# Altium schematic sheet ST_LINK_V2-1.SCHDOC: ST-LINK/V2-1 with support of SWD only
size A4; Date: 29-OCT-2015; Author: A.B; CompanyName: STMicroelectronics; Organization: MCD/TOOLS/GNB; Address1: 12, Rue Jules HOROWITZ; Address2: 38019 Grenoble; Address3: FRANCE; DocumentNumber: MB1225; Revision: B-01; SheetNumber: 2; SheetTotal: 12; Project: STM32F769I-DISCO
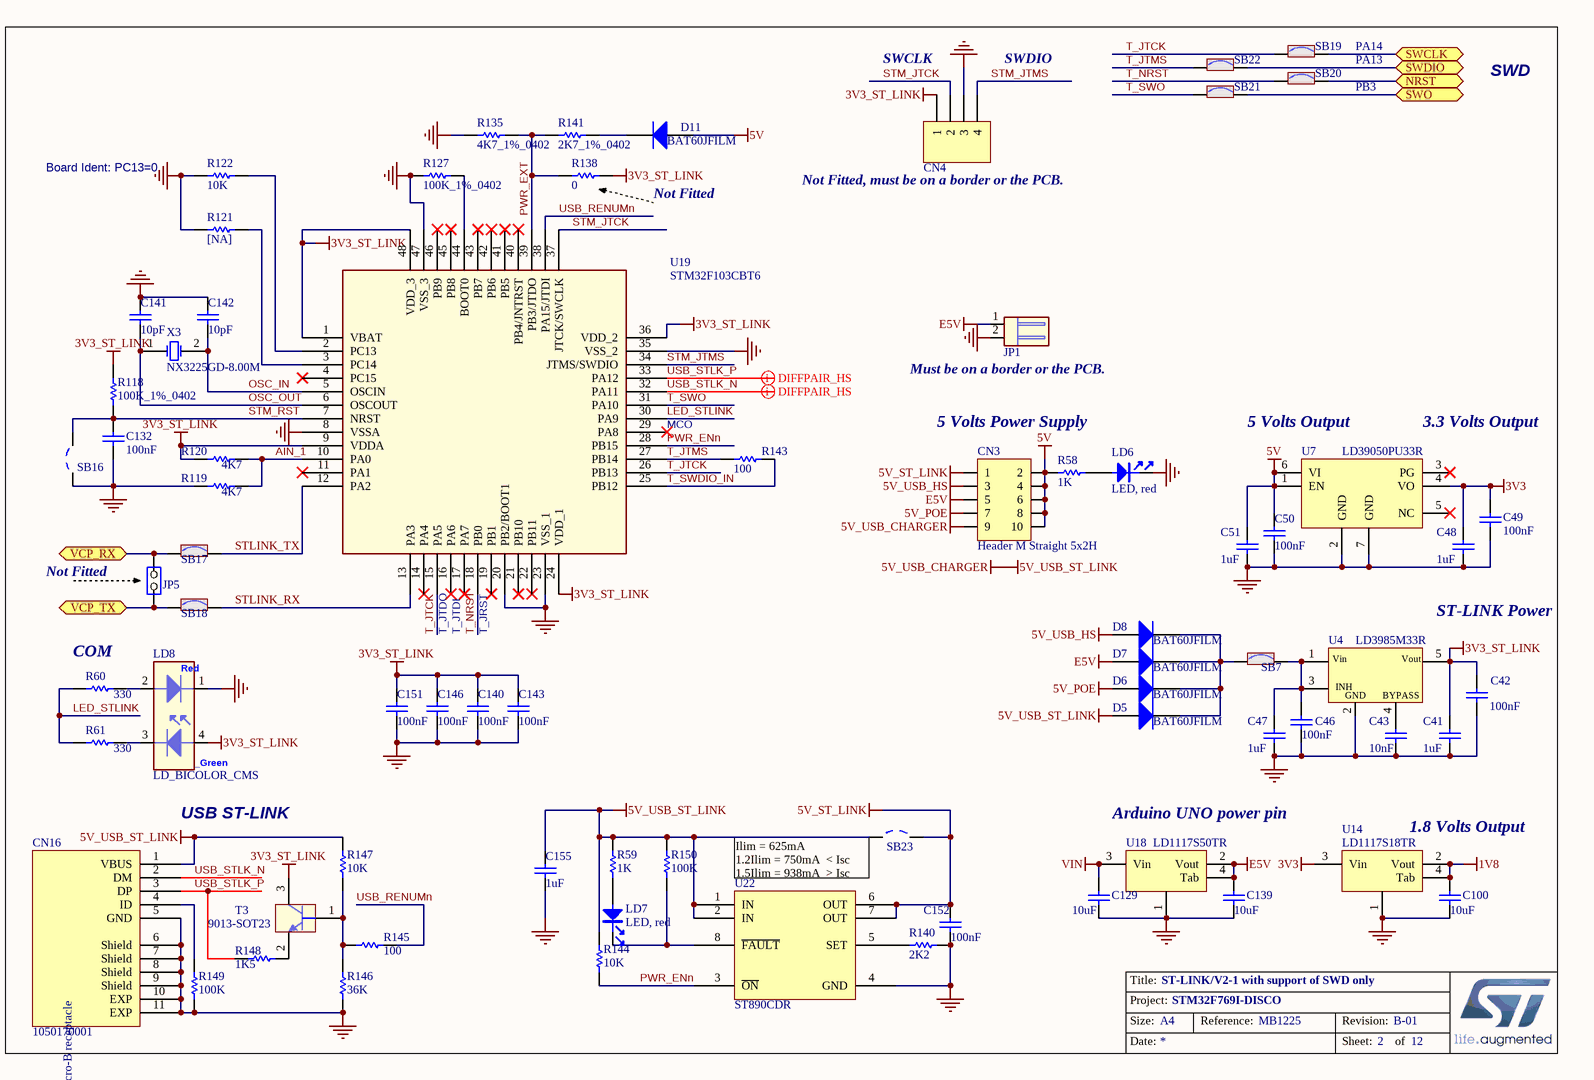
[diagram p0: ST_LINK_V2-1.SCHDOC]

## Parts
C41  1uF  [0603C]
C42  100nF  [0402C]
C43  10nF  [0603C]
C46  100nF  [0402C]
C47  1uF  [0603C]
C48  1uF  [0603C]
C49  100nF  [0402C]
C50  100nF  [0402C]
C51  1uF  [0603C]
C100  10uF  [0603C]
C129  10uF  [0805C]
C132  100nF  [0402C]
C139  10uF  [0805C]
C140  100nF  [0402C]
C141  10pF  [0402C]
C142  10pF  [0402C]
C143  100nF  [0402C]
C146  100nF  [0402C]
C151  100nF  [0402C]
C152  100nF  [0402C]
C155  1uF  [0603C]
CN3  Header M Straight 5x2H  [HDR_2X5_2R54]
CN4  Header 4  [HDR_1X4_2R54]  (value not drawn)
CN16  1050170001  [MICRO_USB_B_105017]
D5  BAT60JFILM  [SOD-323]
D6  BAT60JFILM  [SOD-323]
D7  BAT60JFILM  [SOD-323]
D8  BAT60JFILM  [SOD-323]
D11  BAT60JFILM  [SOD-323]
JP1  WF25402-06421  [HDR_1X2_2R54_RA_11R35]  (value not drawn)
JP5  JP2  [SIP2]  (value not drawn)
LD6  LED, red  [0603D]
LD7  LED, red  [0603D]
LD8  LD_BICOLOR_CMS  [LED2_3528]
R58  1K  [0402R]
R59  1K  [0402R]
R60  330  [0402R]
R61  330  [0402R]
R118  100K_1%_0402  [0402R]
R119  4K7  [0402R]
R120  4K7  [0402R]
R121  [NA]  [0402R]
R122  10K  [0402R]
R127  100K_1%_0402  [0402R]
R135  4K7_1%_0402  [0402R]
R138  0  [0402R]
R140  2K2  [0402R]
R141  2K7_1%_0402  [0402R]
R143  100  [0402R]
R144  10K  [0402R]
R145  100  [0402R]
R146  36K  [0402R]
R147  10K  [0402R]
R148  1K5  [0402R]
R149  100K  [0402R]
R150  100K  [0402R]
SB7  Solder Bridge ON  [JP2_SMD]  (value not drawn)
SB16  Solder Bridge OFF  [JP2_SMD]  (value not drawn)
SB17  Solder Bridge ON  [JP2_SMD]  (value not drawn)
SB18  Solder Bridge ON  [JP2_SMD]  (value not drawn)
SB19  Solder Bridge ON  [JP2_SMD]  (value not drawn)
SB20  Solder Bridge ON  [JP2_SMD]  (value not drawn)
SB21  Solder Bridge ON  [JP2_SMD]  (value not drawn)
SB22  Solder Bridge ON  [JP2_SMD]  (value not drawn)
SB23  Solder Bridge OFF  [JP2_SMD]  (value not drawn)
T3  9013-SOT23  [SOT-23]
U4  LD3985M33R  [SOT-23-5L]
U7  LD39050PU33R  [DFN6_0R95_3X3]
U14  LD1117S18TR  [SOT-223]
U18  LD1117S50TR  [SOT-223]
U19  STM32F103CBT6  [LQFP48_0R5_9X9]
U22  ST890CDR  [SOIC8_1R27_4R9X6]
X3  NX3225GD-8.00M  [XTAL_2SM_3R2X2R5_H1]

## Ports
NRST, SWCLK, SWDIO, SWO, VCP_RX, VCP_TX

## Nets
1V8: C100.2 U14.2(Vout) U14.4(Tab)
3V3: C48.2 C49.2 U7.4(VO) U14.3(Vin)
3V3_ST_LINK: C41.1 C42.2 C140.1 C143.2 C146.2 C151.2 CN4.1 LD8.4 R118.2 R120.1 R138.2 T3.3(C) U4.5(Vout) U19.1(VBAT) U19.9(VDDA) U19.24(VDD_1) U19.36(VDD_2) U19.48(VDD_3)
5V: C50.2 C51.2 CN3.2 CN3.4 CN3.6 CN3.8 CN3.10 D11.1(A) R58.1 U7.1(EN) U7.6(VI)
5V_POE: CN3.7 D6.1(A)
5V_ST_LINK: C152.2 CN3.1 SB23.2 U22.6(OUT) U22.7(OUT)
5V_USB_CHARGER: C155.2 CN3.9 CN16.1(VBUS) D5.1(A) R59.2 R144.2 R147.2 R150.2 SB23.1 U22.1(IN) U22.2(IN)  [also labelled 5V_USB_ST_LINK]
5V_USB_HS: CN3.3 D8.1(A)
E5V: C139.2 CN3.5 D7.1(A) JP1.1 U18.2(Vout) U18.4(Tab)
GND: C41.2 C42.1 C43.1 C46.1 C47.1 C48.1 C49.1 C50.1 C51.1 C100.1 C129.1 C132.1 C139.1 C140.2 C141.1 C142.1 C143.1 C146.1 C151.1 C152.1 C155.1 CN4.3 CN16.5(GND) CN16.6(Shield) CN16.7(Shield) CN16.8(Shield) CN16.9(Shield) CN16.10(EXP) CN16.11(EXP) JP1.2 LD6.2 LD8.1 R119.1 R121.1 R122.1 R127.1 R135.1 R140.2 R146.1 R149.1 SB16.1 U4.2(GND) U7.2(GND) U7.7(GND) U14.1 U18.1 U19.8(VSSA) U19.20(PB2/BOOT1) U19.23(VSS_1) U19.35(VSS_2) U19.47(VSS_3) U22.4(GND)
VIN: C129.2 U18.3(Vin)
AIN_1: R119.2 R120.2 U19.10(PA0)
LED_STLINK: R60.1 R61.1 U19.30(PA9)
NRST: SB20.2 ; port NRST
OSC_IN: C142.2 U19.5(OSCIN) X3.2(OSC2)
OSC_OUT: C141.2 U19.6(OSCOUT) X3.1(OSC1)
PWR_ENn: R144.1 U19.28(PB15) U22.3(~{ON})
PWR_EXT: R135.2 R138.1 R141.1 U19.39(PB3/JTDO)
STLINK_RX: SB18.2 U19.13(PA3)
STLINK_TX: SB17.2 U19.12(PA2)
STM_JTCK: CN4.2 U19.37(JTCK/SWCLK)
STM_JTMS: CN4.4 U19.34(JTMS/SWDIO)
STM_RST: C132.2 R118.1 SB16.2 U19.7(NRST)
SWCLK: SB19.2 ; port SWCLK
SWDIO: SB22.2 ; port SWDIO
SWO: SB21.2 ; port SWO
T_JTCK: SB19.1 U19.15(PA5) U19.26(PB13)
T_JTMS: R143.1 SB22.1 U19.27(PB14)
T_NRST: SB20.1 U19.18(PB0)
T_SWDIO_IN: R143.2 U19.25(PB12)
T_SWO: SB21.1 U19.31(PA10)
USB_RENUMn: R145.2 U19.38(PA15/JTDI)
USB_STLK_N: CN16.2(DM) U19.32(PA11)
USB_STLK_P: CN16.3(DP) R148.1 U19.33(PA12)
VCP_RX: JP5.2(NO) SB17.1 ; port VCP_RX
VCP_TX: JP5.1(COMMON) SB18.1 ; port VCP_TX
NetC43_2: C43.2 U4.4(BYPASS)
NetC46_2: C46.2 C47.2 SB7.2 U4.1(Vin) U4.3(CE)
NetCN16_4: CN16.4(ID) R149.2
NetD5_2: D5.2(K) D6.2(K) D7.2(K) D8.2(K) SB7.1
NetD11_2: D11.2(K) R141.2
NetLD6_1: LD6.1 R58.2
NetLD7_1: LD7.1 R59.1
NetLD7_2: LD7.2 R150.1 U22.8(~{FAULT})
NetLD8_2: LD8.2 R60.2
NetLD8_3: LD8.3 R61.2
NetR121_2: R121.2 U19.3(PC14)
NetR122_2: R122.2 U19.2(PC13)
NetR127_2: R127.2 U19.44(BOOT0)
NetR140_1: R140.1 U22.5(SET)
NetR145_1: R145.1 R146.2 R147.1 T3.1(B)
NetR148_2: R148.2 T3.2(E)

Not connected (* = marked no-connect by the designer): U7 3(PG)* 5(NC)*; U19 4(PC15)* 11(PA1)* 14(PA4)* 16(PA6)* 17(PA7)* 19(PB1)* 21(PB10)* 22(PB11)* 29(PA8)* 40(PB4/JNTRST)* 41(PB5)* 42(PB6)* 43(PB7)* 45(PB8)* 46(PB9)*

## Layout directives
differential pair: USB_STLK_N, USB_STLK_P

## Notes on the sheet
- SWCLK
- SWDIO
- PA14
- PA13
- PB3
- SWD
- Board Ident: PC13=0
- Not Fitted
- (near CN4) Not Fitted, must be on a border or the PCB.
- (near JP1) Must be on a border or the PCB.
- MCO
- 5 Volts Power Supply
- (near U7) 5 Volts Output
- (near U7) 3.3 Volts Output
- (near JP5) Not Fitted
- (near R60) COM
- T_JTDO
- T_JTDI
- T_JRST
- ST-LINK Power
- USB ST-LINK
- (near SB23) Ilim = 625mA
  1.2Ilim = 750mA  < Isc
  1.5Ilim = 938mA  > Isc
- Arduino UNO power pin
- (near U14) 1.8 Volts Output

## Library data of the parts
C41 C47 C48 C51 C155 = Cap_1uF_X5R_10%_0603: Capacitor,1uF,16V,X5R,10%,0603,YAGEO; Manuf_Part_1: CC0603KRX5R7BB105
C42 C46 C49 C50 C132 C140 C143 C146 C151 C152 = Cap_100nF_X7R_10%_0402: Capacitor,100nF,16V,X7R,10%,0402,YAGEO; Manuf_Part_1: CC0402KRX7R7BB104
C43 = Cap_10nF_X7R_10%_0603: Capacitor,10nF,50V,X7R,10%,0603,YAGEO; Manuf_Part_1: CC0603KRX7R9BB103
C100 = Cap_10uF_X5R_10%_0603: Capacitor,10uF,6.3V,X5R,10%,0603,YAGEO; Manuf_Part_1: CC0603KRX5R5BB106
C129 C139 = Cap_10uF_X5R_10%_0805: Capacitor,10uF,25V,X5R,10%,0805,YAGEO; Manuf_Part_1: CC0805KRX5R8BB106
C141 C142 = Cap_10pF_NPO_5%_0402: Capacitor,10pF,50V,NPO,5%,0402,YAGEO; Order: CC0402JRNPO9BN100
CN3 = Header 5X2M: Header Male, 5-Pin, Dual row, Straight, AMD; Manuf_Part_1: 826632-5
CN4 = Header 4: Header, 4-Pin; Fitted: NO
CN16 = 1050170001: USB-MICRO-B, 1050170001, SMT, MOLEX
D5-D8 D11 = BAT60JFILM: Manuf_1: STM; Provided: ST; ECCN_US/EU: EAR99/NEC; Ref St: 9151097
JP1 = JP2_RA: Header, 2-Pins, Single row, Right Angle, 2.54 mm pitch, DIP; Manuf_1: ATOM
JP5 = JP2: Fitted: NO
LD6 LD7 = LED_red: LED, red, 0603; Manuf_1: everlight; Manuf_Part_1: 19-213-R6C-AP1Q2B/3T; Description: LED,red,0603,19-213-R6C-AP1Q2B/3T,everlight; ECCN_US/EU: EAR99/NEC
LD8 = LD_BICOLOR_CMS: Bicolor Led; Manuf_Part_1: HSMF-A201-A00J1; Manuf_1: Avago Technologies; Manuf_2: everluck; Manuf_Part_2: LE-RGW35280; Ref St: xxxxxx; ECCN_US/EU: EAR99/NEC
R58 R59 = Res_1K_1%_0402: Resistor,1K,0402,1%,YAGEO; Manuf_Part_1: RC0402FR-071KL
R60 R61 = Res_330_1%_0402: Resistor,330,0402,1%,YAGEO; Manuf_Part_1: RC0402FR-07330RL
R118 R127 R149 R150 = Res_100K_1%_0402: Resistor,100K,0402,1%,YAGEO; Manuf_Part_1: RC0402FR-07100KL; Manuf_Part_2: RT0402FRE07100KL
R119 R120 R135 = Res_4K7_1%_0402: Resistor,4K7,0402,1%,YAGEO; Manuf_Part_1: RC0402FR-074K7L; Manuf_Part_2: RT0402FRE074K7L
R121 = Res_NA_0402: Resistor,[NA],0402; Fitted: NO
R122 R144 R147 = Res_10K_1%_0402: Resistor,10K,0402,1%,YAGEO; Manuf_Part_1: RC0402FR-0710KL
R138 = Res_0_5%_0402: Resistor,0,0402,5%,YAGEO; Manuf_Part_1: RC0402JR-070RL; Order: 2363467; Fitted: NO
R140 = Res_2K2_1%_0402: Resistor,2K2,0402,1%,YAGEO; Manuf_Part_1: RC0402FR-072K2L
R141 = Res_2K7_1%_0402: Resistor,2K7,0402,1%,YAGEO; Manuf_Part_1: RC0402FR-072K7L
R143 R145 = Res_100_1%_0402: Resistor,100,0402,1%,YAGEO; Manuf_Part_1: RC0402FR-07100RL; Order: 9239111
R146 = Res_36K_1%_0402: Resistor,36K,0402,1%,YAGEO; Manuf_Part_1: RC0402FR-0736KL
R148 = Res_1K5_1%_0402: Resistor,1K5,0402,1%,YAGEO; Manuf_Part_1: RC0402FR-071K5L
SB7 SB17-SB22 = SB_ON: Solder: YES
SB16 SB23 = SB_OFF: Solder: NO
T3 = 9013-SOT23: NPN Bipolar Transistor; Manuf_1: NXP; Manuf_Part_1: BSR14; Description: NPN Bipolar Transistor, SOT-23 Footprint; Order: 1081310; ECCN_US/EU: EAR99/NEC
U4 = LD3985M33R: Ultra low drop-low noise BiCMOS voltage, regulators low ESR capacitors compatible; Manuf_1: STM; Provided: ST; Ref St: 9176161; ECCN_US/EU: EAR99/NEC
U7 = LD39050P: Ultra low drop-low , 500 mA low quiescent current; Manuf_1: STM; Provided: ST; ECCN_US/EU: EAR99/NEC; Ref St: xxxxxxxx
U14 = LD1117S18TR: LOW DROP FIXED AND ADJUSTABLE POSITIVE VOLTAGE REGULATORS (1.8 Volts); Manuf_1: STM; Ref St: 9176180; ECCN_US/EU: EAR99/NEC; Provided: ST
U18 = LD1117S50TR: IC REG LDO 5V 0.8A SOT223; Manuf_1: STM; Ordered by: ST; ECCN_US/EU: EAR99/NEC; Ref St: 9176133
U19 = STM32F103CBT6: Medium-density performance line ARM-based 32-bit MCU with 128KB Flash; Manuf_1: STM; Ref St: xxxxxxxx; Provided: ST; ECCN_US/EU: 3A991A2/NEC
U22 = ST890CDR: 1.2 A current limited high-side power switch with thermal shutdown; Manuf_1: STM; ECCN_US/EU: EAR99/NEC; Provided: ST
X3 = XTAL_8M_NX3225GD: Crystal 8Mhz, 8pF, -+50PPM, SMD; Manuf_1: NDK; Manuf_Part_1: NX3225GD 8MHz EXS00A-CG04874; Manuf_Part_2: NX3225GD-8.000M-STD-CRA-3; ECCN_US/EU: EAR99/NEC; NDK Ref: X3127326; Ref St: 9157029; Provided: ST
